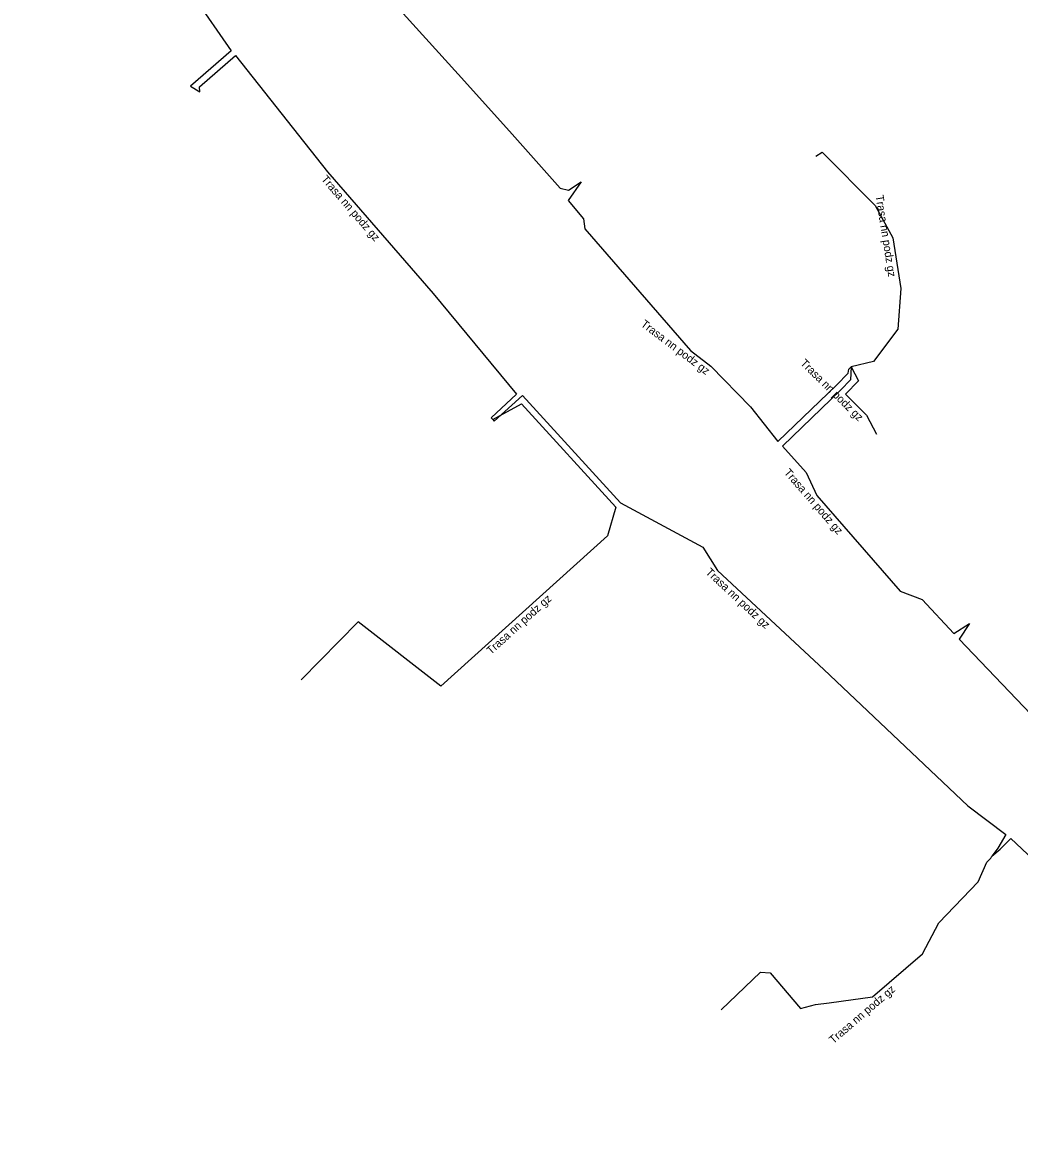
# Model space of a CAD drawing. Extents: x -484846 to -484244, y -1128177 to -1127608.
# Drawn here: x -484541.7 to -484479.3, y -1128042.5 to -1127972.3 of the extents above; entities that cross this region are included whole.
import ezdxf

# ---------------------------------------------------------------- set-up
doc = ezdxf.new("R2010")
doc.units = 0
doc.layers.add('Popiskový text - Ostatní atributy Trasy', color=7, linetype='Continuous')
doc.layers.add('Spojnice NN', color=7, linetype='Continuous')

msp = doc.modelspace()

# ---------------------------------------------------------------- linework, layer by layer
at = {"layer": 'Spojnice NN'}
for points in [[(-484529.035, -1127955.968), (-484529.034, -1127956.51), (-484529.623, -1127956.51), (-484529.861, -1127956.407), (-484530.96, -1127956.96), (-484531.02, -1127958.2), (-484529.91, -1127959.88), (-484527.05, -1127964.26), (-484524.04, -1127967.67), (-484523.69, -1127968.43), (-484522.775, -1127969.093), (-484521.501, -1127968.785), (-484520.49, -1127968.799), (-484514.426, -1127975.5), (-484511.217, -1127979.06), (-484508.053, -1127982.62), (-484507.526, -1127982.752), (-484506.74, -1127982.232)], [(-484541.353, -1127962.502), (-484541.157, -1127962.364), (-484541.65, -1127961.74), (-484538.3, -1127959.51), (-484536.72, -1127961.87), (-484533.23, -1127967.36), (-484528.601, -1127974.029), (-484531.157, -1127976.244), (-484530.575, -1127976.61)], [(-484530.575, -1127976.61), (-484530.593, -1127976.284), (-484528.339, -1127974.331), (-484522.58, -1127981.59), (-484515.99, -1127989.2), (-484510.786, -1127995.497), (-484512.357, -1127996.968), (-484512.265, -1127997.076)], [(-484492.071, -1127980.626), (-484491.67, -1127980.38), (-484488.36, -1127983.71), (-484487.27, -1127985.72), (-484486.77, -1127988.88), (-484486.96, -1127991.43), (-484488.46, -1127993.44), (-484489.867, -1127993.786)], [(-484506.74, -1127982.232), (-484507.559, -1127983.399), (-484506.6, -1127984.53), (-484506.5, -1127985.15), (-484499.9, -1127992.77), (-484498.63, -1127993.73), (-484496.16, -1127996.29), (-484494.438, -1127998.442), (-484490.792, -1127994.926), (-484490.056, -1127994.175), (-484490.016, -1127993.919), (-484489.867, -1127993.786)], [(-484489.867, -1127993.786), (-484489.909, -1127994.588), (-484490.51, -1127995.21), (-484494.16, -1127998.73), (-484492.68, -1128000.39), (-484492.01, -1128001.81), (-484486.81, -1128007.79), (-484485.42, -1128008.32), (-484483.449, -1128010.437), (-484482.47, -1128009.81)], [(-484489.867, -1127993.786), (-484489.415, -1127994.664), (-484490.228, -1127995.494), (-484488.9, -1127996.8), (-484488.277, -1127997.996)], [(-484512.265, -1127997.076), (-484512.17, -1127997.183), (-484510.413, -1127995.575), (-484504.282, -1128002.285), (-484499.13, -1128005.04), (-484498.22, -1128006.5), (-484491.57, -1128012.69), (-484482.57, -1128021.2), (-484480.204, -1128022.999), (-484480.701, -1128023.859), (-484481.071, -1128024.348)], [(-484512.265, -1127997.076), (-484510.475, -1127996.101), (-484504.578, -1128002.555), (-484505.1, -1128004.34), (-484515.5, -1128013.73), (-484520.68, -1128009.71), (-484524.229, -1128013.34)], [(-484482.47, -1128009.81), (-484483.126, -1128010.797), (-484473.27, -1128021.1), (-484472.75, -1128022.88), (-484469.654, -1128026.326), (-484467.278, -1128026.071), (-484467.024, -1128026.17)], [(-484481.071, -1128024.348), (-484480.55, -1128023.907), (-484479.88, -1128023.25), (-484461.492, -1128040.542), (-484462.273, -1128042.494)], [(-484497.986, -1128033.946), (-484495.53, -1128031.6), (-484494.93, -1128031.64), (-484493.03, -1128033.88), (-484492.1, -1128033.62), (-484491.24, -1128033.52), (-484490.49, -1128033.42), (-484488.53, -1128033.14), (-484485.41, -1128030.46), (-484484.38, -1128028.51), (-484481.92, -1128025.95), (-484481.39, -1128024.72), (-484481.13, -1128024.47), (-484481.071, -1128024.348)]]:
    msp.add_lwpolyline(points, dxfattribs=at)

# ---------------------------------------------------------------- texts
at = {"layer": 'Popiskový text - Ostatní atributy Trasy'}
for rotation, p in [(310.89144, (-484523.016, -1127982.079)), (278.99125, (-484488.343, -1127983.092)), (322.91416, (-484503.054, -1127991.2)), (315.47854, (-484493.081, -1127993.599)), (311.00909, (-484494.093, -1128000.406)), (317.05178, (-484498.997, -1128006.664)), (42.07839, (-484512.38, -1128011.79)), (40.66173, (-484490.984, -1128036.105))]:
    msp.add_text('Trasa nn podz gz', height=0.5, rotation=rotation, dxfattribs=at).set_placement(p)

doc.saveas('drawing.dxf')
